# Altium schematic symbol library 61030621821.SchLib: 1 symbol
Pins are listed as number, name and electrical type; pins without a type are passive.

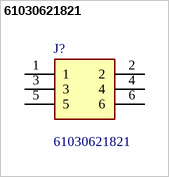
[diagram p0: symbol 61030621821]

## 61030621821
designator J?
WURTH ELEKTRONIK - 61030621821 - Board-To-Board Connector, 2.54 mm, 6 Contacts, Receptacle, WR-PHD Series, Surface Mount, 2 Rows; Geometry.Height: 7.75mm
footprint 61030621821
pins: 1, 2, 3, 4, 5, 6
